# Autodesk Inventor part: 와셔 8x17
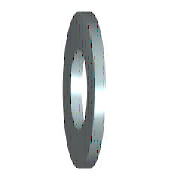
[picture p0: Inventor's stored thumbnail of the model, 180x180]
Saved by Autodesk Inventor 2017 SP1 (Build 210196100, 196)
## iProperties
Created: 2012-02
Part Number: 와셔 8x17
Material: 강철, 연강
Description: 평면 와셔
Document SubType Name: Modeling
Standard: KS B 1326
Designer: mduedu
Standards Organization: KS
Language: ko-KR
Size Designation: 8x17
Categories: <MemberInstance><Categories><Category DisplayName="조임쇠" InternalName="e4da775c-781d-43d5-af7c-5136215cf5a6" Mnemonic="FSTN"><Category DisplayName="와셔" InternalN
Density: 7.85 g/cm^3
Appearance: 파란색 - 벽 페인트 - 광택
Mass: 2.05184 g
Surface Area: 4.57416 cm^2
Volume: 0.261381 cm^3
IsCustomPart: 1
Author: mduedu
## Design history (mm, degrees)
sketch "스케치"
  geometry: C1 r 8.5 at (0, 0); C2 r 4.5 at (0, 0); 1 further point
  constraints: 2 centre point, 2 coincident
  dimensions: "d0" = 9 diameter of C2 (= SD1); "d1" = 17 diameter of C1 (= SD2)
extrude "본체" new body sketch "스케치" distance "d2" = 1.6 (= SD); taper "d3" = 0 deg
workaxis "Work Axis1"
workplane "Work Plane1"
body "Solid1"
other parameters: "SD1" = 9 [user parameter; used in 1 equation term], "SD2" = 17 [user parameter; used in 1 equation term], "SD" = 1.6 [user parameter; used in 1 equation term], "d4" = 0, "d5" = 0, "d6" = 0, "d7" = 0, "NND" = 8 [user parameter]
